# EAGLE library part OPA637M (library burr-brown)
Difet(R) Operational Amplifiers Precision, High-Speed
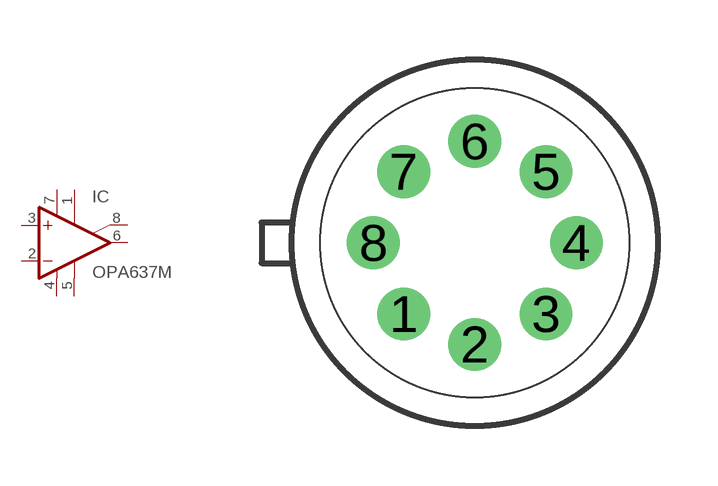
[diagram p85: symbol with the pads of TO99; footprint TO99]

Designator prefix IC

## OPA637M (MPN: OPA637AM; OC_FARNELL: 1459640; OC_NEWARK: 61M8069)  [TO99]
1  TRIM1  pas
2  -IN  in
3  +IN  in
4  V-  pwr
5  TRIM2  pas
6  OUT  out
7  V+  pwr
8  CASE  pas

## Footprint TO99 (pad centres in mm)
Metal can Package
drill 0.813 round: 1 -1.778,-1.778; 2 0,-2.54; 3 1.778,-1.778; 4 2.54,0; 5 1.778,1.778; 6 0,2.54; 7 -1.778,1.778; 8 -2.54,0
